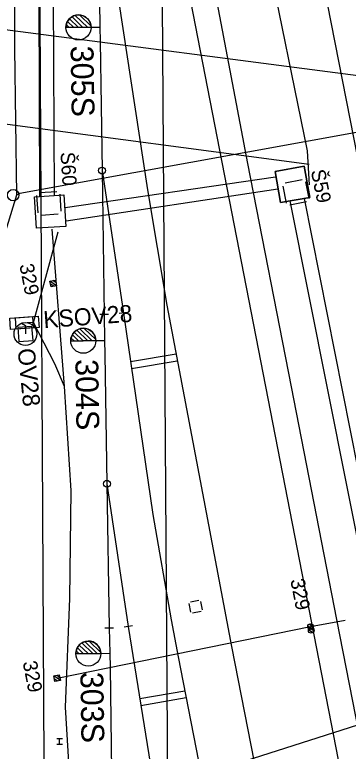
# Model space of a CAD drawing. Extents: x -545846 to -545044, y -1122650 to -1119108.
# Drawn here: x -545618.9 to -545589.6, y -1120012.2 to -1119947.6 of the extents above; entities that cross this region are included whole.
import ezdxf

# ---------------------------------------------------------------- set-up
doc = ezdxf.new("R2010")
doc.units = 0
for name, color, linetype in [('osvětlené plochy-hodnota-obrys', 7, 'Continuous'), ('Vrstva 1', 7, 'Continuous'), ('Vrstva 11', 7, 'Continuous'), ('Vrstva 12', 7, 'Continuous'), ('Vrstva 12 - Trakce zaklady', 7, 'Continuous'), ('Vrstva 2', 7, 'Continuous'), ('Vrstva 25', 7, 'Continuous'), ('Vrstva 26', 7, 'Continuous'), ('Vrstva 31', 7, 'Continuous'), ('Vrstva 34', 7, 'Continuous'), ('Vrstva 35', 7, 'Continuous'), ('Vrstva 36', 7, 'Continuous'), ('Vrstva 41', 7, 'Continuous'), ('Vrstva 43', 7, 'Continuous'), ('Vrstva 44', 7, 'Continuous'), ('Vrstva 63', 7, 'Continuous'), ('Vrstva 7', 7, 'Continuous')]:
    doc.layers.add(name, color=color, linetype=linetype)

msp = doc.modelspace()

# ---------------------------------------------------------------- linework, layer by layer
at = {"layer": 'osvětlené plochy-hodnota-obrys'}
for points in [[(-545615.946, -1120078.595), (-545617.001, -1119876.724)], [(-545604.967, -1120087.817), (-545606.006, -1119933.661)], [(-545605.8, -1119934.355), (-545489.142, -1120534.587)]]:
    msp.add_lwpolyline(points, dxfattribs=at)
at = {"layer": 'Vrstva 1'}
for p, q in [((-545611.437, -1119946.424), (-545611.401, -1119948.677)), ((-545611.212, -1119961.264), (-545609.349, -1119973.764)), ((-545611.023, -1119973.891), (-545610.986, -1119976.17)), ((-545610.787, -1119988.743), (-545608.92, -1120001.258)), ((-545610.588, -1120001.378), (-545610.545, -1120003.605))]:
    msp.add_line(p, q, dxfattribs=at)
for points in [[(-545608.646, -1119843.243), (-545607.968, -1119853.947), (-545604.823, -1119878.324), (-545603.305, -1119886.455), (-545599.914, -1119903.772), (-545596.132, -1119922.876), (-545592.141, -1119943.299), (-545588.525, -1119961.8), (-545584.866, -1119980.43), (-545581.323, -1119998.614), (-545578.302, -1120014.333), (-545574.804, -1120032.326), (-545570.752, -1120053.023), (-545566.972, -1120072.457), (-545563.466, -1120090.434), (-545562.18, -1120097.022)], [(-545606.489, -1119916.134), (-545602.042, -1119941.851), (-545598.462, -1119960.658), (-545594.656, -1119980.253), (-545590.686, -1120000.64), (-545587.651, -1120016.178), (-545584.022, -1120034.678), (-545580.073, -1120054.893), (-545576.301, -1120074.138), (-545572.767, -1120092.238), (-545571.478, -1120098.833)], [(-545609.773, -1119946.287), (-545607.246, -1119962.958), (-545605.546, -1119973.067), (-545602.299, -1119990.174), (-545599.861, -1120003.011), (-545595.351, -1120026.149), (-545592.088, -1120042.905), (-545589.326, -1120057.082), (-545585.714, -1120075.648), (-545581.397, -1120097.788), (-545580.84, -1120100.656)], [(-545611.401, -1119948.677), (-545611.377, -1119949.902), (-545611.212, -1119961.264), (-545611.023, -1119973.891)], [(-545609.349, -1119973.764), (-545606.766, -1119991.45), (-545605.151, -1120000.686), (-545604.54, -1120003.913), (-545600.08, -1120026.893), (-545596.768, -1120044.006), (-545594.04, -1120057.971), (-545590.384, -1120076.827), (-545586.111, -1120098.754), (-545585.561, -1120101.575)], [(-545610.986, -1119976.17), (-545610.967, -1119977.381), (-545610.787, -1119988.743), (-545610.588, -1120001.378)], [(-545608.92, -1120001.258), (-545605.448, -1120022.876), (-545604.409, -1120028.503), (-545601.548, -1120043.573), (-545599.24, -1120055.486), (-545596.038, -1120071.891), (-545594.862, -1120077.975), (-545590.095, -1120102.458)], [(-545610.545, -1120003.605), (-545610.517, -1120004.869), (-545610.354, -1120016.231), (-545610.162, -1120028.86)]]:
    msp.add_lwpolyline(points, dxfattribs=at)
at = {"layer": 'Vrstva 11'}
for p, q in [((-545615.192, -1119971.365), (-545615.777, -1119970.971)), ((-545615.452, -1119971.416), (-545615.726, -1119971.231)), ((-545615.241, -1119971.106), (-545615.519, -1119970.919)), ((-545592.812, -1120001.485), (-545593.19, -1120001.23)), ((-545592.758, -1120001.81), (-545593.137, -1120001.555)), ((-545592.704, -1120001.331), (-545593.088, -1120001.072)), ((-545592.651, -1120001.656), (-545593.035, -1120001.398)), ((-545614.862, -1120006.001), (-545615.447, -1120005.607)), ((-545615.122, -1120006.052), (-545615.396, -1120005.867)), ((-545614.911, -1120005.742), (-545615.189, -1120005.555)), ((-545614.684, -1120011.113), (-545615.184, -1120011.113)), ((-545614.934, -1120011.613), (-545614.934, -1120011.113)), ((-545614.684, -1120011.613), (-545615.184, -1120011.613))]:
    msp.add_line(p, q, dxfattribs=at)
for points in [[(-545615.682, -1119971.46), (-545615.777, -1119970.969), (-545615.286, -1119970.874), (-545615.191, -1119971.365)], [(-545615.351, -1120006.096), (-545615.447, -1120005.606), (-545614.957, -1120005.51), (-545614.861, -1120006)]]:
    msp.add_lwpolyline(points, close=True, dxfattribs=at)
for points in [[(-545615.682, -1119971.46), (-545615.777, -1119970.969), (-545615.286, -1119970.874), (-545615.191, -1119971.365), (-545615.682, -1119971.46)], [(-545615.154, -1120005.803), (-545592.946, -1120001.276), (-545589.909, -1120000.713)], [(-545615.351, -1120006.096), (-545615.447, -1120005.606), (-545614.957, -1120005.51), (-545614.861, -1120006), (-545615.351, -1120006.096)]]:
    msp.add_lwpolyline(points, dxfattribs=at)
for centre in [(-545592.946, -1120001.276), (-545592.893, -1120001.601)]:
    msp.add_circle(centre, 0.25, dxfattribs=at)
at = {"layer": 'Vrstva 12'}
msp.add_lwpolyline([(-545618.6, -1119975.04), (-545618.5, -1119976.27), (-545617.25, -1119976.16), (-545617.37, -1119974.95), (-545618.6, -1119975.04)], dxfattribs=at)
at = {"layer": 'Vrstva 12 - Trakce zaklady'}
msp.add_lwpolyline([(-545618.6, -1119975.04), (-545618.5, -1119976.27), (-545617.25, -1119976.16), (-545617.37, -1119974.95), (-545618.6, -1119975.04)], dxfattribs=at)
at = {"layer": 'Vrstva 2'}
for p, q in [((-545613.287, -1119948.709), (-545614.065, -1119947.955)), ((-545612.889, -1119948.703), (-545613.846, -1119947.776)), ((-545612.491, -1119948.697), (-545613.568, -1119947.654)), ((-545612.18, -1119948.607), (-545613.202, -1119947.616)), ((-545614.083, -1119948.721), (-545614.339, -1119948.473)), ((-545613.684, -1119948.715), (-545614.231, -1119948.185)), ((-545614.368, -1119948.726), (-545612.173, -1119948.691)), ((-545612.173, -1119948.692), (-545614.368, -1119948.726)), ((-545612.173, -1119948.691), (-545612.173, -1119948.692)), ((-545612.172, -1119948.692), (-545611.401, -1119948.677)), ((-545611.212, -1119961.264), (-545609.349, -1119973.764)), ((-545608.978, -1119973.71), (-545609.72, -1119973.818)), ((-545610.648, -1119973.885), (-545611.398, -1119973.897)), ((-545612.076, -1119976.19), (-545613.153, -1119975.148)), ((-545611.765, -1119976.1), (-545612.788, -1119975.109)), ((-545613.269, -1119976.209), (-545613.817, -1119975.679)), ((-545612.872, -1119976.202), (-545613.65, -1119975.449)), ((-545612.474, -1119976.196), (-545613.431, -1119975.27)), ((-545613.953, -1119976.22), (-545611.758, -1119976.184)), ((-545611.758, -1119976.185), (-545613.953, -1119976.22)), ((-545613.668, -1119976.215), (-545613.924, -1119975.966)), ((-545611.758, -1119976.184), (-545611.758, -1119976.185)), ((-545611.757, -1119976.185), (-545610.986, -1119976.17)), ((-545610.787, -1119988.743), (-545608.92, -1120001.258)), ((-545610.963, -1120001.385), (-545610.213, -1120001.371)), ((-545608.55, -1120001.199), (-545609.29, -1120001.317)), ((-545612.431, -1120003.643), (-545613.211, -1120002.892)), ((-545612.033, -1120003.636), (-545612.993, -1120002.712)), ((-545611.635, -1120003.628), (-545612.715, -1120002.589)), ((-545611.324, -1120003.538), (-545612.35, -1120002.55)), ((-545613.226, -1120003.658), (-545613.484, -1120003.41)), ((-545612.828, -1120003.651), (-545613.377, -1120003.123)), ((-545613.511, -1120003.664), (-545611.317, -1120003.621)), ((-545611.317, -1120003.622), (-545613.511, -1120003.664)), ((-545611.317, -1120003.621), (-545611.317, -1120003.622)), ((-545611.316, -1120003.622), (-545610.545, -1120003.605))]:
    msp.add_line(p, q, dxfattribs=at)
for points in [[(-545611.401, -1119948.677), (-545611.377, -1119949.902), (-545611.212, -1119961.264), (-545611.023, -1119973.891)], [(-545610.986, -1119976.17), (-545610.967, -1119977.381), (-545610.787, -1119988.743), (-545610.588, -1120001.378)], [(-545610.545, -1120003.605), (-545610.517, -1120004.869), (-545610.354, -1120016.231), (-545610.162, -1120028.86)]]:
    msp.add_lwpolyline(points, dxfattribs=at)
for centre, radius in [((-545613.276, -1119948.708), 1.097), ((-545611.212, -1119961.264), 0.3), ((-545612.861, -1119976.201), 1.097), ((-545610.787, -1119988.743), 0.3), ((-545612.42, -1120003.642), 1.097)]:
    msp.add_circle(centre, radius, dxfattribs=at)
for centre, start, end in [((-545613.27, -1119948.709), 0.93501, 180.89586), ((-545612.855, -1119976.202), 0.9497, 180.91055), ((-545612.414, -1120003.643), 1.12573, 181.08658)]:
    msp.add_arc(centre, 1.098, start, end, dxfattribs=at)
at = {"layer": 'Vrstva 25'}
for points in [[(-545617.309, -1119974.068), (-545617.236, -1119975.066), (-545619.231, -1119975.212), (-545619.304, -1119974.214), (-545617.309, -1119974.068)], [(-545616.809, -1119974.038), (-545616.736, -1119975.036), (-545618.731, -1119975.182), (-545618.804, -1119974.184), (-545616.809, -1119974.038)]]:
    msp.add_lwpolyline(points, dxfattribs=at)
msp.add_circle((-545617.926, -1119975.599), 1, dxfattribs=at)
at = {"layer": 'Vrstva 26'}
for points in [[(-545593.05, -1119962.526), (-545593.214, -1119959.543), (-545596.804, -1119941.892), (-545598.291, -1119933.129), (-545596.928, -1119931.519), (-545597.041, -1119930.893), (-545599.968, -1119928.522), (-545602.342, -1119915.51), (-545605.949, -1119897.26), (-545607.861, -1119887.619), (-545608.325, -1119885.109), (-545607.716, -1119884.036), (-545607.766, -1119883.859), (-545607.875, -1119883.53), (-545607.678, -1119883.109)], [(-545617.232, -1119974.592), (-545615.045, -1119966.65)], [(-545612.253, -1120084.91), (-545612.347, -1120083.201), (-545612.831, -1120078.348), (-545613.117, -1120073.242), (-545612.801, -1120069.259), (-545613.277, -1120062.623), (-545613.395, -1120049.699), (-545613.129, -1120040.608), (-545613.346, -1120029.64), (-545613.367, -1120027.079), (-545613.105, -1120023.59), (-545613.561, -1120022.31), (-545614.415, -1120008.344), (-545614.025, -1119998.801), (-545613.917, -1119989.343), (-545614.504, -1119980.224), (-545615.353, -1119978.229), (-545617.232, -1119974.592), (-545617.77, -1119974.61), (-545618.27, -1119974.64), (-545617.92, -1119974.86), (-545617.926, -1119975.599)]]:
    msp.add_lwpolyline(points, dxfattribs=at)
at = {"layer": 'Vrstva 31'}
for points in [[(-545627.409, -1120054.201), (-545627.847, -1120048.986), (-545625.34, -1120049.11), (-545613.395, -1120049.699), (-545613.129, -1120040.608), (-545613.367, -1120027.079), (-545613.105, -1120023.59), (-545613.561, -1120022.31), (-545614.415, -1120008.344), (-545614.025, -1119998.801), (-545613.917, -1119989.343), (-545614.504, -1119980.224), (-545615.59, -1119966.397)], [(-545613.395, -1120049.699), (-545613.129, -1120040.608), (-545613.346, -1120029.64), (-545613.367, -1120027.079), (-545613.105, -1120023.59), (-545613.561, -1120022.31), (-545614.415, -1120008.344), (-545614.025, -1119998.801), (-545613.917, -1119989.343), (-545614.504, -1119980.224), (-545615.353, -1119978.229), (-545617.232, -1119974.592), (-545615.045, -1119966.65)]]:
    msp.add_lwpolyline(points, dxfattribs=at)
at = {"layer": 'Vrstva 34'}
for p, q in [((-545595.167, -1119962.353), (-545593.697, -1119962.055)), ((-545595.064, -1119964.118), (-545595.362, -1119962.648)), ((-545593.402, -1119962.25), (-545593.104, -1119963.72)), ((-545616.819, -1119964.964), (-545616.913, -1119963.467)), ((-545616.679, -1119963.202), (-545615.182, -1119963.108)), ((-545614.917, -1119963.342), (-545614.823, -1119964.839)), ((-545593.299, -1119964.015), (-545594.769, -1119964.313)), ((-545615.057, -1119965.104), (-545616.554, -1119965.198))]:
    msp.add_line(p, q, dxfattribs=at)
at = {"layer": 'Vrstva 35'}
for p, q in [((-545616.666, -1119963.523), (-545616.876, -1119910.248)), ((-545615.385, -1119963.439), (-545615.675, -1119910.235)), ((-545596.01, -1119961.841), (-545614.444, -1119964.531)), ((-545595.828, -1119962.896), (-545614.352, -1119965.711)), ((-545586.108, -1120007.335), (-545594.749, -1119963.936)), ((-545584.92, -1120007.097), (-545593.471, -1119963.704))]:
    msp.add_line(p, q, dxfattribs=at)
at = {"layer": 'Vrstva 36'}
msp.add_lwpolyline([(-545596.039, -1119961.348), (-545593.51, -1119960.882), (-545593.014, -1119963.615), (-545595.57, -1119964.079)], close=True, dxfattribs=at)
for points in [[(-545593.51, -1119960.882), (-545596.039, -1119961.348), (-545595.57, -1119964.079), (-545593.014, -1119963.615), (-545593.51, -1119960.882)], [(-545593.51, -1119960.882), (-545593.51, -1119960.882)], [(-545596.039, -1119961.348), (-545596.039, -1119961.348)], [(-545617.135, -1119963.556), (-545614.558, -1119963.386), (-545614.378, -1119966.169), (-545616.97, -1119966.328), (-545617.135, -1119963.556)], [(-545617.135, -1119963.556), (-545614.558, -1119963.386), (-545614.378, -1119966.169), (-545616.97, -1119966.328), (-545617.135, -1119963.556)], [(-545614.558, -1119963.386), (-545614.558, -1119963.386)], [(-545617.135, -1119963.556), (-545617.135, -1119963.556)], [(-545595.57, -1119964.079), (-545595.57, -1119964.079)], [(-545593.014, -1119963.615), (-545593.014, -1119963.615)], [(-545616.97, -1119966.328), (-545616.97, -1119966.328)], [(-545614.378, -1119966.169), (-545614.378, -1119966.169)]]:
    msp.add_lwpolyline(points, dxfattribs=at)
at = {"layer": 'Vrstva 41'}
for p, q in [((-545603.473, -1119999.11), (-545602.737, -1119998.966)), ((-545602.59, -1119999.065), (-545602.446, -1119999.801)), ((-545603.428, -1119999.993), (-545603.572, -1119999.257)), ((-545602.545, -1119999.948), (-545603.281, -1120000.092))]:
    msp.add_line(p, q, dxfattribs=at)
at = {"layer": 'Vrstva 43'}
msp.add_circle((-545618.996, -1119963.419), 0.5, dxfattribs=at)
at = {"layer": 'Vrstva 44'}
for points in [[(-545654.9, -1119582.222), (-545645.965, -1119631.818), (-545637.145, -1119681.816), (-545629.836, -1119730.566), (-545626.416, -1119761.521), (-545622.849, -1119813.009), (-545619.592, -1119863.304), (-545618.858, -1119914.175), (-545618.881, -1119950.565), (-545618.715, -1119963.415), (-545629.02, -1119997.179)], [(-545573.151, -1119955.055), (-545618.404, -1119963.283), (-545618.715, -1119963.415)]]:
    msp.add_lwpolyline(points, dxfattribs=at)
at = {"layer": 'Vrstva 63'}
for p, q in [((-545510.939, -1119963.064), (-545651.669, -1119944.771)), ((-545593.066, -1119960.74), (-545656.192, -1119952.346)), ((-545583.044, -1120008.072), (-545662.585, -1120033.421))]:
    msp.add_line(p, q, dxfattribs=at)
at = {"layer": 'Vrstva 7'}
for p, q in [((-545608.727, -1119978.026), (-545604.732, -1119977.355)), ((-545608.64, -1119978.62), (-545604.62, -1119977.945)), ((-545607.902, -1120007.595), (-545603.961, -1120006.896)), ((-545607.807, -1120008.188), (-545603.847, -1120007.485))]:
    msp.add_line(p, q, dxfattribs=at)

# ---------------------------------------------------------------- texts
at = {"layer": 'Vrstva 11'}
for rotation, p in [(281.0172, (-545618.458, -1119969.554)), (281.07113, (-545594.728, -1119997.186)), (281.04899, (-545618.173, -1120004.404))]:
    msp.add_text('329', height=1.25, rotation=rotation, dxfattribs=at).set_placement(p)
at = {"layer": 'Vrstva 2'}
for s, p in [('305S', (-545613.969, -1119950.326)), ('304S', (-545613.554, -1119977.819)), ('303S', (-545613.113, -1120005.254))]:
    msp.add_text(s, height=2, rotation=270.92645, dxfattribs=at).set_placement(p)
at = {"layer": 'Vrstva 25'}
for s, rotation, p in [('KSOV28', 4.18492, (-545616.303, -1119975.094)), ('OV28', 275.66371, (-545618.613, -1119976.929))]:
    msp.add_text(s, height=1.5, rotation=rotation, dxfattribs=at).set_placement(p)
at = {"layer": 'Vrstva 34'}
for s, rotation, p in [('Š60', 273.60957, (-545614.855, -1119959.671)), ('Š59', 281.49271, (-545592.932, -1119961.291))]:
    msp.add_text(s, height=1.25, rotation=rotation, dxfattribs=at).set_placement(p)

doc.saveas('drawing.dxf')
